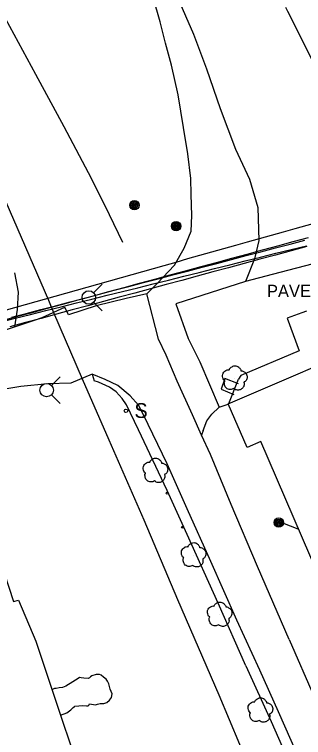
# Model space of a CAD drawing. Extents: x 368532 to 392481, y 10654822 to 10676899.
# Drawn here: x 378313.7 to 378431.1, y 10661427.9 to 10661721.4 of the extents above; entities that cross this region are included whole.
import ezdxf

# ---------------------------------------------------------------- set-up
doc = ezdxf.new("R2010")
doc.units = 0
for name, color, linetype in [('p_Catenary', 7, 'Continuous'), ('p_dtm sidewalk', 7, 'Continuous'), ('p_dtm slab', 7, 'Continuous'), ('p_railroad rr control', 7, 'Continuous'), ('p_road - paved curb', 7, 'Continuous'), ('p_road dirt road', 7, 'Continuous'), ('p_road general road feature', 7, 'Continuous'), ('p_structure building', 7, 'Continuous'), ('p_structure sign', 7, 'Continuous'), ('p_structure stairs', 7, 'Continuous'), ('p_structure unidentified', 7, 'Continuous'), ('p_utility general pole', 7, 'Continuous'), ('p_veg tree', 7, 'Continuous')]:
    doc.layers.add(name, color=color, linetype=linetype)

msp = doc.modelspace()

# ---------------------------------------------------------------- linework, layer by layer
at = {"layer": 'p_Catenary'}
for points in [[(378423.71, 10661724.34), (378426.29, 10661719.22), (378428.86, 10661714.11), (378431.44, 10661708.99), (378434.01, 10661703.88), (378436.59, 10661698.76), (378439.16, 10661693.65), (378441.73, 10661688.53), (378444.31, 10661683.42), (378446.88, 10661678.3), (378449.46, 10661673.19), (378452.03, 10661668.07), (378454.61, 10661662.96), (378457.18, 10661657.84), (378459.76, 10661652.73), (378462.33, 10661647.61), (378464.91, 10661642.5)], [(378465.5, 10661641.8), (378462.95, 10661646.85), (378460.39, 10661651.9), (378457.84, 10661656.96), (378455.29, 10661662.01), (378452.74, 10661667.06), (378450.19, 10661672.11), (378447.64, 10661677.17), (378445.08, 10661682.22), (378442.53, 10661687.27), (378439.98, 10661692.32), (378437.43, 10661697.38), (378434.88, 10661702.43), (378432.33, 10661707.48), (378429.78, 10661712.53), (378427.22, 10661717.59), (378424.67, 10661722.64)], [(378282, 10661593.48), (378330.28, 10661607.1), (378374.49, 10661619.56), (378379.33, 10661620.93), (378384.17, 10661622.29), (378389.01, 10661623.65), (378393.85, 10661625.02), (378398.69, 10661626.38), (378403.53, 10661627.74), (378408.37, 10661629.11), (378413.21, 10661630.47), (378418.05, 10661631.83), (378422.89, 10661633.2), (378427.73, 10661634.56), (378432.57, 10661635.92), (378437.41, 10661637.29), (378442.25, 10661638.65), (378447.09, 10661640.01), (378451.93, 10661641.38), (378456.77, 10661642.74), (378461.61, 10661644.11)], [(378308.4, 10661597.05), (378314.63, 10661598.74), (378320.87, 10661600.44), (378327.1, 10661602.13), (378333.33, 10661603.83), (378339.57, 10661605.52), (378345.8, 10661607.21), (378352.04, 10661608.91), (378358.27, 10661610.6), (378364.51, 10661612.3), (378370.74, 10661613.99), (378376.98, 10661615.68), (378383.21, 10661617.38), (378389.45, 10661619.07), (378395.68, 10661620.77), (378401.92, 10661622.46), (378408.15, 10661624.15), (378414.38, 10661625.85), (378420.62, 10661627.54), (378426.85, 10661629.24), (378433.09, 10661630.93)], [(378307.85, 10661596.55), (378314.08, 10661598.1), (378320.3, 10661599.65), (378326.52, 10661601.2), (378332.74, 10661602.75), (378338.97, 10661604.3), (378345.19, 10661605.85), (378351.41, 10661607.4), (378357.63, 10661608.95), (378363.85, 10661610.5), (378370.08, 10661612.05), (378376.3, 10661613.6), (378382.52, 10661615.15), (378388.74, 10661616.7), (378394.97, 10661618.25), (378401.19, 10661619.8), (378407.41, 10661621.35), (378413.63, 10661622.9), (378419.86, 10661624.45), (378426.08, 10661626), (378432.3, 10661627.55)], [(378432.36, 10661627.18), (378426.02, 10661625.46), (378419.68, 10661623.75), (378413.33, 10661622.03), (378406.99, 10661620.32), (378400.65, 10661618.6), (378394.3, 10661616.89), (378387.96, 10661615.18), (378381.62, 10661613.46), (378375.27, 10661611.75), (378368.93, 10661610.03), (378362.59, 10661608.32), (378356.24, 10661606.6), (378349.9, 10661604.89), (378343.56, 10661603.17), (378337.21, 10661601.46), (378330.87, 10661599.75), (378324.53, 10661598.03), (378318.18, 10661596.32), (378311.84, 10661594.6)], [(378312.5, 10661598.5), (378318.45, 10661600.06), (378324.41, 10661601.62), (378330.36, 10661603.19), (378336.32, 10661604.75), (378342.28, 10661606.31), (378348.23, 10661607.88), (378354.19, 10661609.44), (378360.14, 10661611), (378366.1, 10661612.57), (378372.05, 10661614.13), (378378.01, 10661615.69), (378383.96, 10661617.25), (378389.92, 10661618.82), (378395.87, 10661620.38), (378401.83, 10661621.94), (378407.78, 10661623.51), (378413.74, 10661625.07), (378419.7, 10661626.63), (378425.65, 10661628.2), (378431.61, 10661629.76)], [(378422.21, 10661515.17), (378422.55, 10661515.03), (378422.9, 10661514.89), (378423.24, 10661514.75), (378423.58, 10661514.61), (378423.92, 10661514.48), (378424.27, 10661514.34), (378424.61, 10661514.2), (378424.95, 10661514.06), (378425.29, 10661513.93), (378425.64, 10661513.79), (378425.98, 10661513.65), (378426.32, 10661513.51), (378426.67, 10661513.38), (378427.01, 10661513.24), (378427.35, 10661513.1), (378427.69, 10661512.96), (378428.04, 10661512.82), (378428.38, 10661512.69), (378428.72, 10661512.55)]]:
    msp.add_lwpolyline(points, dxfattribs=at)
at = {"layer": 'p_dtm sidewalk'}
for p, q in [((378345.26, 10661575.35), (378346.16, 10661572.64)), ((378347.79, 10661572.11), (378346.16, 10661572.64)), ((378352.36, 10661570.12), (378347.79, 10661572.11)), ((378355.06, 10661568.18), (378352.36, 10661570.12)), ((378357.45, 10661565.51), (378355.06, 10661568.18)), ((378359.17, 10661562.94), (378357.45, 10661565.51)), ((378364.14, 10661552.8), (378359.17, 10661562.94)), ((378375.76, 10661528.18), (378364.14, 10661552.8)), ((378383.87, 10661510.27), (378375.76, 10661528.18)), ((378396.37, 10661482.37), (378383.87, 10661510.27)), ((378407.65, 10661457.01), (378396.37, 10661482.37)), ((378407.65, 10661457.01), (378417.9, 10661434.42)), ((378417.9, 10661434.42), (378428.67, 10661410.13))]:
    msp.add_line(p, q, dxfattribs=at)
at = {"layer": 'p_dtm slab'}
for p, q in [((378339.63, 10661451.84), (378336.4, 10661449.82)), ((378340.2, 10661452.2), (378339.63, 10661451.84)), ((378340.83, 10661452.1), (378340.2, 10661452.2)), ((378341.87, 10661451.96), (378340.83, 10661452.1)), ((378343.66, 10661451.85), (378341.87, 10661451.96)), ((378344.21, 10661452.08), (378343.66, 10661451.85)), ((378344.62, 10661452.51), (378344.21, 10661452.08)), ((378345.2, 10661452.96), (378344.62, 10661452.51)), ((378346.96, 10661453.52), (378345.2, 10661452.96)), ((378348.25, 10661453.49), (378346.96, 10661453.52)), ((378348.94, 10661453.22), (378348.25, 10661453.49)), ((378349.9, 10661452.4), (378348.94, 10661453.22)), ((378350.92, 10661451.6), (378349.9, 10661452.4)), ((378351.53, 10661450.72), (378350.92, 10661451.6)), ((378333.21, 10661448.24), (378331.9, 10661448.01)), ((378334.55, 10661448.8), (378333.21, 10661448.24)), ((378335.61, 10661449.35), (378334.55, 10661448.8)), ((378336.4, 10661449.82), (378335.61, 10661449.35)), ((378352.02, 10661449.62), (378351.53, 10661450.72)), ((378352.64, 10661447.58), (378352.02, 10661449.62)), ((378329.95, 10661447.77), (378328.96, 10661447.31)), ((378330.62, 10661447.85), (378329.95, 10661447.77)), ((378331.9, 10661448.01), (378330.62, 10661447.85)), ((378353.39, 10661445.62), (378352.64, 10661447.58)), ((378353.14, 10661444.18), (378353.39, 10661445.62)), ((378351.17, 10661442.16), (378352.25, 10661443.05)), ((378352.25, 10661443.05), (378353.14, 10661444.18)), ((378336.57, 10661439.17), (378337.52, 10661440.04)), ((378337.52, 10661440.04), (378338.1, 10661440.44)), ((378338.1, 10661440.44), (378338.31, 10661440.56)), ((378338.31, 10661440.56), (378341.53, 10661440.86)), ((378341.53, 10661440.86), (378342.94, 10661440.76)), ((378342.94, 10661440.76), (378343.58, 10661440.78)), ((378343.58, 10661440.78), (378343.97, 10661441.08)), ((378343.97, 10661441.08), (378344.26, 10661441.56)), ((378344.26, 10661441.56), (378346.67, 10661441.1)), ((378346.67, 10661441.1), (378347.4, 10661441.46)), ((378347.4, 10661441.46), (378348.55, 10661441.69)), ((378348.55, 10661441.69), (378350, 10661441.71)), ((378350, 10661441.71), (378351.17, 10661442.16)), ((378332.41, 10661436.99), (378334.95, 10661437.91)), ((378334.95, 10661437.91), (378336.57, 10661439.17))]:
    msp.add_line(p, q, dxfattribs=at)
at = {"layer": 'p_railroad rr control'}
for p, q in [((378345.87, 10661608.42), (378349.37, 10661611.95)), ((378345.85, 10661604.6), (378349.37, 10661601.07)), ((378328.76, 10661570.81), (378332.26, 10661574.34)), ((378328.73, 10661566.99), (378332.26, 10661563.46))]:
    msp.add_line(p, q, dxfattribs=at)
for points in [[(378396.77, 10661445.07), (378380.11, 10661483.72), (378366.42, 10661516.07), (378352.16, 10661548.63), (378341.38, 10661573.39), (378329.69, 10661600.35), (378327.66, 10661605.36), (378310.38, 10661645.28), (378297.51, 10661675.14), (378281.09, 10661712.37), (378271.72, 10661733.43), (378251.42, 10661775.47), (378234.51, 10661809.47), (378214.12, 10661848.42), (378192.9, 10661888.86), (378170.23, 10661933.48)], [(378357.74, 10661628.83), (378352.37, 10661640.12), (378345.04, 10661654.86), (378333.91, 10661675.77), (378322.45, 10661697.07), (378310.16, 10661719.75), (378306.17, 10661727.2), (378303.04, 10661733.34), (378298.61, 10661741.85), (378291.46, 10661755.15), (378277.66, 10661780.69), (378264.24, 10661805.64), (378259.72, 10661814.26)], [(378591.5, 10660992.56), (378566.85, 10661050.05), (378542.52, 10661106.37), (378517.03, 10661164.76), (378489.61, 10661228.49), (378459.64, 10661298.61), (378432.27, 10661362.29), (378409.47, 10661415.04), (378396.77, 10661445.07)]]:
    msp.add_lwpolyline(points, dxfattribs=at)
for centre in [(378343.92, 10661606.53), (378326.81, 10661568.92)]:
    msp.add_circle(centre, 2.73, dxfattribs=at)
at = {"layer": 'p_road - paved curb'}
for p, q in [((378367.46, 10661607.96), (378359.06, 10661606.12)), ((378372.2, 10661589.58), (378367.46, 10661607.96)), ((378359.06, 10661606.12), (378346.97, 10661603.07)), ((378325.02, 10661598.44), (378334.24, 10661602.55)), ((378335.65, 10661599.43), (378334.24, 10661602.55)), ((378346.97, 10661603.07), (378335.65, 10661599.43)), ((378321.86, 10661597.37), (378325.02, 10661598.44)), ((378313.82, 10661594.6), (378321.86, 10661597.37)), ((378303.09, 10661591.13), (378313.82, 10661594.6)), ((378375.31, 10661583.05), (378372.2, 10661589.58)), ((378379.84, 10661572.53), (378375.31, 10661583.05)), ((378345.26, 10661575.35), (378336.59, 10661571.74)), ((378350.61, 10661573.21), (378345.26, 10661575.35)), ((378327.26, 10661571.41), (378316.28, 10661570.36)), ((378336.59, 10661571.74), (378327.26, 10661571.41)), ((378355.74, 10661570.78), (378350.61, 10661573.21)), ((378385.99, 10661558.84), (378379.84, 10661572.53)), ((378316.28, 10661570.36), (378309.07, 10661569.19)), ((378360.68, 10661566.59), (378355.74, 10661570.78)), ((378364.05, 10661562.82), (378360.68, 10661566.59)), ((378366.06, 10661558.93), (378364.05, 10661562.82)), ((378375.78, 10661539.04), (378366.06, 10661558.93)), ((378389.68, 10661550.58), (378385.99, 10661558.84)), ((378393.24, 10661542.72), (378389.68, 10661550.58)), ((378401.7, 10661522.54), (378393.24, 10661542.72)), ((378383.82, 10661520.67), (378375.78, 10661539.04)), ((378412.37, 10661497.3), (378401.7, 10661522.54)), ((378393.46, 10661499.28), (378383.82, 10661520.67)), ((378403.99, 10661475.53), (378393.46, 10661499.28)), ((378425.24, 10661467.66), (378412.37, 10661497.3)), ((378413.28, 10661455.24), (378403.99, 10661475.53)), ((378425.24, 10661467.66), (378435.4, 10661444.47)), ((378420.95, 10661438.29), (378413.28, 10661455.24)), ((378429.64, 10661418.62), (378420.95, 10661438.29))]:
    msp.add_line(p, q, dxfattribs=at)
at = {"layer": 'p_road dirt road'}
for p, q in [((378372.92, 10661718.37), (378368.73, 10661732.75)), ((378379.66, 10661729.02), (378386.41, 10661713.37)), ((378375.11, 10661709.72), (378372.92, 10661718.37)), ((378386.41, 10661713.37), (378391.74, 10661699.32)), ((378377.5, 10661700.81), (378375.11, 10661709.72)), ((378380.21, 10661688.8), (378377.5, 10661700.81)), ((378391.74, 10661699.32), (378397.27, 10661683.31)), ((378382.4, 10661675.5), (378380.21, 10661688.8)), ((378397.27, 10661683.31), (378403.49, 10661666.76)), ((378384.11, 10661664.84), (378382.4, 10661675.5)), ((378403.49, 10661666.76), (378409.13, 10661654.57)), ((378385.26, 10661654.79), (378384.11, 10661664.84)), ((378385.46, 10661648.3), (378385.26, 10661654.79)), ((378409.13, 10661654.57), (378412.54, 10661643)), ((378385.79, 10661639.84), (378385.46, 10661648.3)), ((378412.54, 10661643), (378412.92, 10661629.68)), ((378385.4, 10661633.47), (378385.79, 10661639.84)), ((378382.63, 10661626.57), (378385.4, 10661633.47)), ((378412.92, 10661629.68), (378411.2, 10661622.19)), ((378378.66, 10661619.69), (378382.63, 10661626.57)), ((378411.2, 10661622.19), (378407.53, 10661612.96)), ((378371.69, 10661612.25), (378378.66, 10661619.69)), ((378313.7, 10661616.56), (378315.2, 10661608.66)), ((378367.46, 10661607.96), (378371.69, 10661612.25)), ((378315.2, 10661608.66), (378314.88, 10661601.68)), ((378314.88, 10661601.68), (378313.82, 10661594.6)), ((378393.79, 10661559.13), (378396.85, 10661561.97)), ((378391.81, 10661556.49), (378393.79, 10661559.13)), ((378390.3, 10661552.56), (378391.81, 10661556.49)), ((378390.3, 10661552.56), (378389.68, 10661550.58))]:
    msp.add_line(p, q, dxfattribs=at)
at = {"layer": 'p_road general road feature'}
for p, q in [((378438.72, 10661621.17), (378418.37, 10661615.79)), ((378418.37, 10661615.79), (378407.53, 10661612.96)), ((378407.53, 10661612.96), (378379.2, 10661603.9)), ((378379.2, 10661603.9), (378384.26, 10661589.88)), ((378432.23, 10661601.03), (378430.42, 10661600.36)), ((378430.42, 10661600.36), (378424.48, 10661598.12)), ((378424.48, 10661598.12), (378429.32, 10661584.86)), ((378384.26, 10661589.88), (378388.93, 10661580.36)), ((378429.32, 10661584.86), (378405.58, 10661574.84)), ((378388.93, 10661580.36), (378396.85, 10661561.97)), ((378405.58, 10661574.84), (378404.66, 10661573.36)), ((378400.76, 10661563.52), (378404.66, 10661573.36)), ((378396.85, 10661561.97), (378400.53, 10661563.27))]:
    msp.add_line(p, q, dxfattribs=at)
at = {"layer": 'p_structure building'}
for points in [[(378491.25, 10661381.2), (378465.63, 10661440.92), (378460.62, 10661439.14), (378413.79, 10661548.01), (378408.2, 10661545.6), (378400.47, 10661563.4), (378462.33, 10661589.89), (378469.97, 10661571.33), (378464.62, 10661568.87), (378510.7, 10661461.25), (378506.18, 10661459.09), (378527.57, 10661408.8)], [(378237.31, 10661543.53), (378288.02, 10661560.4), (378313.39, 10661483.09), (378315.33, 10661483.71), (378322.42, 10661467.03), (378322.54, 10661466.53), (378346.74, 10661394.1), (378300.07, 10661378.61), (378272.34, 10661464.63), (378264.56, 10661461.79)]]:
    msp.add_lwpolyline(points, dxfattribs=at)
at = {"layer": 'p_structure sign'}
msp.add_circle((378358.98, 10661560.53), 0.713, dxfattribs=at)
at = {"layer": 'p_structure stairs'}
for p, q in [((378399.09, 10661573.58), (378397.58, 10661569.26)), ((378404.73, 10661571.47), (378399.09, 10661573.58)), ((378397.58, 10661569.26), (378402.83, 10661567.09))]:
    msp.add_line(p, q, dxfattribs=at)
at = {"layer": 'p_structure unidentified'}
for centre in [(378375.73, 10661527.1), (378381.91, 10661513.24)]:
    msp.add_circle(centre, 0.375, dxfattribs=at)
at = {"layer": 'p_utility general pole'}
for centre, radius in [((378362.41, 10661643.97), 1.9), ((378362.41, 10661643.97), 1.44), ((378362.41, 10661643.97), 0.973), ((378362.41, 10661643.97), 0.539), ((378362.41, 10661643.97), 0.192), ((378379.36, 10661635.49), 1.9), ((378379.36, 10661635.49), 1.44), ((378379.36, 10661635.49), 0.973), ((378379.36, 10661635.49), 0.539), ((378379.36, 10661635.49), 0.192), ((378421.01, 10661515.12), 1.9), ((378421.01, 10661515.12), 1.44), ((378421.01, 10661515.12), 0.973), ((378421.01, 10661515.12), 0.539), ((378421.01, 10661515.12), 0.192)]:
    msp.add_circle(centre, radius, dxfattribs=at)
at = {"layer": 'p_veg tree'}
for p, q in [((378403.13, 10661573.69), (378403.13, 10661573.69)), ((378370.93, 10661536.19), (378370.93, 10661536.19)), ((378386.42, 10661501.9), (378386.42, 10661501.9)), ((378396.99, 10661477.79), (378396.99, 10661477.79)), ((378413.51, 10661438.9), (378413.51, 10661438.9))]:
    msp.add_line(p, q, dxfattribs=at)
for points in [[(378402.79, 10661569.54), (378401.29, 10661569.12), (378399.79, 10661569.71), (378399.03, 10661571), (378398.91, 10661571.85), (378399.07, 10661572.53), (378399.14, 10661572.66), (378399.06, 10661572.74), (378398.45, 10661573.48), (378398.27, 10661575.4), (378399.5, 10661576.87), (378400.77, 10661577.14), (378400.92, 10661577.14), (378400.96, 10661577.25), (378401.69, 10661578.22), (378403.21, 10661578.78), (378404.78, 10661578.22), (378405.46, 10661577.37), (378405.67, 10661576.86), (378405.68, 10661576.75), (378405.79, 10661576.78), (378406.44, 10661576.65), (378407.52, 10661575.95), (378408.16, 10661574.52), (378407.89, 10661573.15), (378407.14, 10661572.29), (378406.91, 10661572.16), (378406.87, 10661572.1), (378406.88, 10661572.04), (378406.95, 10661571.59), (378406.88, 10661570.62), (378406.19, 10661569.62), (378405.1, 10661568.98), (378403.51, 10661569.1), (378402.77, 10661569.54)], [(378370.59, 10661532.04), (378369.09, 10661531.62), (378367.59, 10661532.21), (378366.83, 10661533.51), (378366.71, 10661534.35), (378366.87, 10661535.03), (378366.94, 10661535.17), (378366.86, 10661535.24), (378366.26, 10661535.99), (378366.07, 10661537.91), (378367.3, 10661539.37), (378368.57, 10661539.65), (378368.72, 10661539.64), (378368.76, 10661539.75), (378369.5, 10661540.72), (378371.01, 10661541.29), (378372.59, 10661540.72), (378373.27, 10661539.87), (378373.47, 10661539.36), (378373.49, 10661539.25), (378373.59, 10661539.28), (378374.25, 10661539.16), (378375.32, 10661538.45), (378375.96, 10661537.02), (378375.69, 10661535.65), (378374.94, 10661534.8), (378374.71, 10661534.67), (378374.68, 10661534.61), (378374.68, 10661534.54), (378374.75, 10661534.09), (378374.68, 10661533.12), (378373.99, 10661532.12), (378372.91, 10661531.48), (378371.31, 10661531.6), (378370.57, 10661532.04)], [(378386.08, 10661497.75), (378384.58, 10661497.33), (378383.08, 10661497.92), (378382.32, 10661499.22), (378382.2, 10661500.06), (378382.36, 10661500.74), (378382.43, 10661500.88), (378382.35, 10661500.95), (378381.74, 10661501.7), (378381.56, 10661503.62), (378382.79, 10661505.08), (378384.06, 10661505.36), (378384.21, 10661505.35), (378384.25, 10661505.46), (378384.98, 10661506.43), (378386.5, 10661507), (378388.08, 10661506.43), (378388.75, 10661505.58), (378388.96, 10661505.07), (378388.98, 10661504.96), (378389.08, 10661504.99), (378389.73, 10661504.87), (378390.81, 10661504.16), (378391.45, 10661502.73), (378391.18, 10661501.36), (378390.43, 10661500.51), (378390.2, 10661500.38), (378390.16, 10661500.32), (378390.17, 10661500.25), (378390.24, 10661499.8), (378390.17, 10661498.83), (378389.48, 10661497.83), (378388.39, 10661497.19), (378386.8, 10661497.31), (378386.06, 10661497.75)], [(378396.66, 10661473.64), (378395.16, 10661473.23), (378393.65, 10661473.81), (378392.89, 10661475.11), (378392.77, 10661475.95), (378392.93, 10661476.64), (378393, 10661476.77), (378392.92, 10661476.84), (378392.32, 10661477.59), (378392.13, 10661479.51), (378393.36, 10661480.98), (378394.63, 10661481.25), (378394.78, 10661481.24), (378394.82, 10661481.36), (378395.56, 10661482.33), (378397.07, 10661482.89), (378398.65, 10661482.33), (378399.33, 10661481.48), (378399.53, 10661480.97), (378399.55, 10661480.85), (378399.65, 10661480.89), (378400.31, 10661480.76), (378401.38, 10661480.06), (378402.02, 10661478.62), (378401.75, 10661477.26), (378401, 10661476.4), (378400.77, 10661476.27), (378400.74, 10661476.21), (378400.75, 10661476.14), (378400.81, 10661475.7), (378400.74, 10661474.72), (378400.05, 10661473.73), (378398.97, 10661473.08), (378397.37, 10661473.2), (378396.63, 10661473.65)], [(378413.18, 10661434.75), (378411.68, 10661434.33), (378410.18, 10661434.91), (378409.42, 10661436.21), (378409.29, 10661437.05), (378409.46, 10661437.74), (378409.52, 10661437.87), (378409.44, 10661437.94), (378408.84, 10661438.69), (378408.65, 10661440.61), (378409.88, 10661442.08), (378411.15, 10661442.35), (378411.3, 10661442.34), (378411.34, 10661442.46), (378412.07, 10661443.43), (378413.59, 10661443.99), (378415.17, 10661443.43), (378415.84, 10661442.58), (378416.05, 10661442.07), (378416.07, 10661441.96), (378416.17, 10661441.99), (378416.83, 10661441.87), (378417.9, 10661441.16), (378418.54, 10661439.73), (378418.27, 10661438.36), (378417.53, 10661437.51), (378417.3, 10661437.38), (378417.26, 10661437.32), (378417.27, 10661437.25), (378417.34, 10661436.8), (378417.27, 10661435.83), (378416.58, 10661434.83), (378415.49, 10661434.19), (378413.9, 10661434.31), (378413.16, 10661434.75)]]:
    msp.add_spline(points, degree=3, dxfattribs=at)

# ---------------------------------------------------------------- texts
at = {"layer": 'p_road general road feature'}
msp.add_text(' PAVED PARKING', height=5, dxfattribs=at).set_placement((378414.37, 10661606.68))
at = {"layer": 'p_structure sign'}
msp.add_text('S', height=6, dxfattribs=at).set_placement((378362.44, 10661557.63))

doc.saveas('drawing.dxf')
